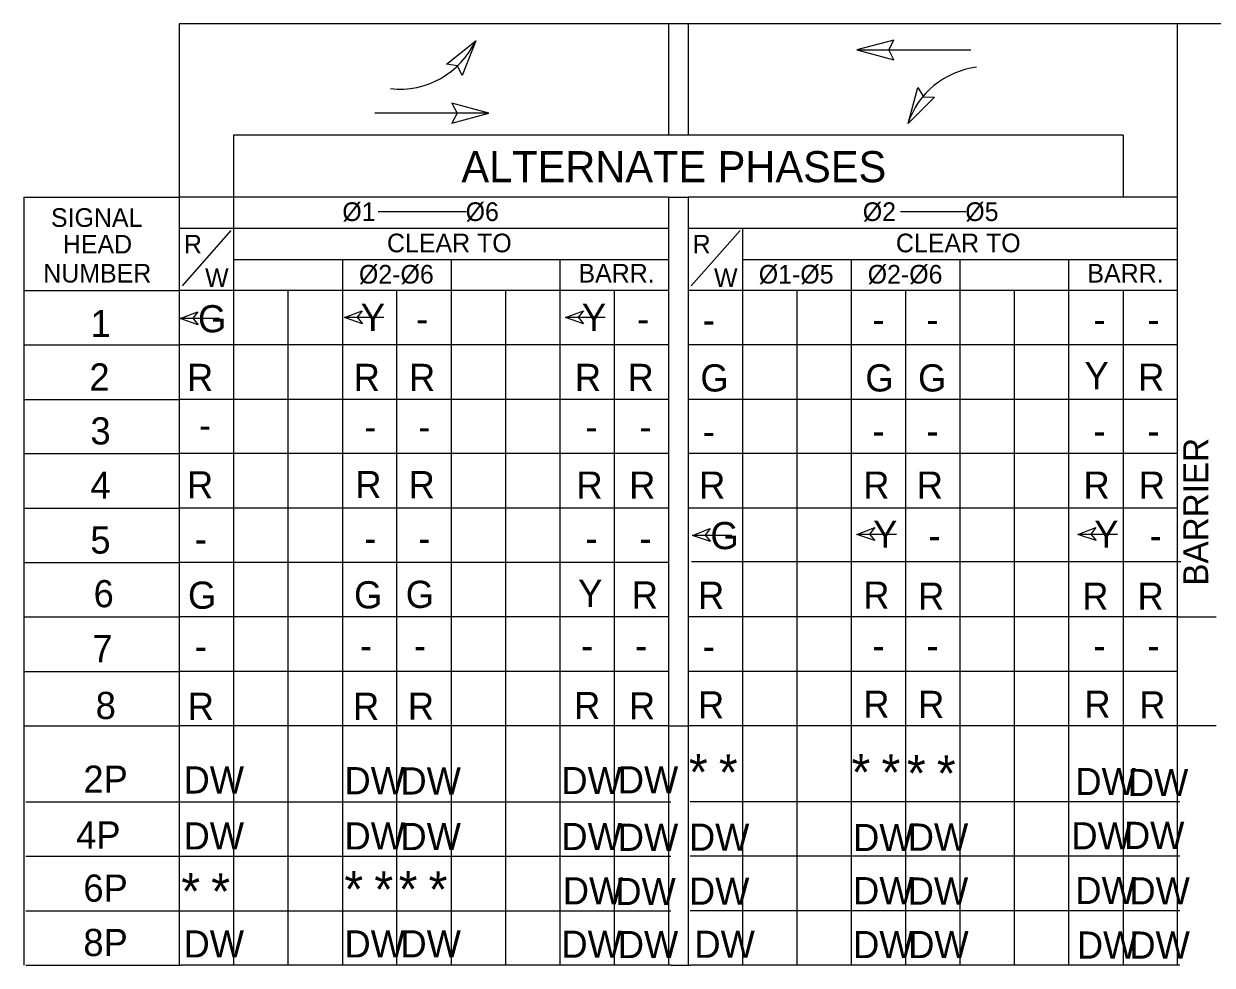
# Model space of a CAD drawing. Extents: x 0 to 3.01, y -0.05 to 1.83.
# Drawn here: x 2.3322 to 2.6407, y 1.0091 to 1.2534 of the extents above; entities that cross this region are included whole.
import ezdxf

# ---------------------------------------------------------------- set-up
doc = ezdxf.new("R2010")
doc.units = 0
for name, color, linetype in [('TR_TS_Border', 7, 'Continuous'), ('TR_TS_Phase1', 7, 'Continuous'), ('TR_TS_Phase2', 7, 'Continuous'), ('TR_TS_Phase3', 7, 'Continuous'), ('TR_TS_Phase4', 7, 'Continuous'), ('TR_TS_Phase5', 7, 'Continuous'), ('TR_TS_Phase6', 7, 'Continuous'), ('TR_TS_Phase7', 7, 'Continuous'), ('TR_TS_Phase8', 7, 'Continuous')]:
    doc.layers.add(name, color=color, linetype=linetype)

msp = doc.modelspace()

# ---------------------------------------------------------------- linework, layer by layer
at = {"layer": 'TR_TS_Border'}
for p, q in [((2.372526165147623, 1.2534462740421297), (2.372526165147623, 1.2084390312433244)), ((2.900956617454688, 1.2534462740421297), (2.372526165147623, 1.2534462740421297)), ((2.4995983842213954, 1.2534461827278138), (2.4995983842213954, 1.2245734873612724)), ((2.504660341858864, 1.2534461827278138), (2.504660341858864, 1.2245734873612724)), ((2.6317323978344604, 1.009138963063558), (2.6317323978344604, 1.2534462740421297)), ((2.6176014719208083, 1.2245736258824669), (2.3866570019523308, 1.2245736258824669)), ((2.3866570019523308, 1.2245736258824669), (2.3866570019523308, 1.2003716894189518)), ((2.6176014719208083, 1.2245736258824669), (2.6176014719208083, 1.2084390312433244)), ((2.332189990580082, 1.2084390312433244), (2.372526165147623, 1.2084390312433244)), ((2.332189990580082, 1.2084390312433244), (2.372526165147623, 1.2084390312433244)), ((2.332189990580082, 1.2084390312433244), (2.332189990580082, 1.009138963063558)), ((2.49959827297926, 1.2084390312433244), (2.372526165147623, 1.2084390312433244)), ((2.372526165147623, 1.2084390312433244), (2.372526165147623, 1.009138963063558)), ((2.49959827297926, 1.2084390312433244), (2.5046602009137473, 1.2084390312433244)), ((2.4995983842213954, 1.2084389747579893), (2.4995983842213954, 1.0091388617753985)), ((2.6317323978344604, 1.2084390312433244), (2.5046602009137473, 1.2084390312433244)), ((2.504660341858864, 1.2084389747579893), (2.504660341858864, 1.0091388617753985)), ((2.424163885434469, 1.2046953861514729), (2.447127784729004, 1.2046953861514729)), ((2.559788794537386, 1.2046953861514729), (2.5768168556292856, 1.2046953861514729)), ((2.372526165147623, 1.2003716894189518), (2.49959827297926, 1.2003716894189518)), ((2.3866570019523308, 1.2003716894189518), (2.3866570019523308, 1.009138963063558)), ((2.5046602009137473, 1.2003716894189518), (2.6317323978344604, 1.2003716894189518)), ((2.5187911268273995, 1.2003716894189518), (2.5187911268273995, 1.009138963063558)), ((2.3733699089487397, 1.185449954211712), (2.3860771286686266, 1.1998447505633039)), ((2.5055037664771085, 1.185449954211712), (2.518158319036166, 1.1998447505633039)), ((2.3866570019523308, 1.192304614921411), (2.49959827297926, 1.192304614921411)), ((2.41491876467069, 1.192304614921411), (2.41491876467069, 1.009138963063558)), ((2.4431276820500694, 1.192304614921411), (2.4431276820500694, 1.009138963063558)), ((2.471389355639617, 1.192304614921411), (2.471389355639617, 1.009138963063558)), ((2.5187911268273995, 1.192304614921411), (2.6317323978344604, 1.192304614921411)), ((2.547000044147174, 1.192304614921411), (2.547000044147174, 1.009138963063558)), ((2.575208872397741, 1.192304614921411), (2.575208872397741, 1.009138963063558)), ((2.6034706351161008, 1.192304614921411), (2.6034706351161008, 1.009138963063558)), ((2.332189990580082, 1.1842374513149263), (2.372526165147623, 1.1842374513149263)), ((2.332189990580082, 1.1842374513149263), (2.372526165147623, 1.1842374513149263)), ((2.49959827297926, 1.1842374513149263), (2.372526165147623, 1.1842374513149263)), ((2.4007879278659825, 1.1842374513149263), (2.4007879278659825, 1.009138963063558)), ((2.4289967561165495, 1.1842374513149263), (2.4289967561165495, 1.009138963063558)), ((2.457258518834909, 1.1842374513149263), (2.457258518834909, 1.009138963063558)), ((2.485467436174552, 1.1842374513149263), (2.485467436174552, 1.009138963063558)), ((2.6317323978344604, 1.1842374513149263), (2.5046602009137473, 1.1842374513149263)), ((2.5328691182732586, 1.1842374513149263), (2.5328691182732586, 1.009138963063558)), ((2.5611308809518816, 1.1842374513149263), (2.5611308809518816, 1.009138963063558)), ((2.589339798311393, 1.1842374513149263), (2.589339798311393, 1.009138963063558)), ((2.6176014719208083, 1.1842374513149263), (2.6176014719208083, 1.009138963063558)), ((2.332189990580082, 1.1701066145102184), (2.372526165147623, 1.1701066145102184)), ((2.49959827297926, 1.1701066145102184), (2.372526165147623, 1.1701066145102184)), ((2.6317323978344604, 1.1701066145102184), (2.5046602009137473, 1.1701066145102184)), ((2.332189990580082, 1.155975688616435), (2.372526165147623, 1.155975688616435)), ((2.49959827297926, 1.155975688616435), (2.372526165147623, 1.155975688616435)), ((2.6317323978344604, 1.155975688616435), (2.5046602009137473, 1.155975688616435)), ((2.332189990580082, 1.1418975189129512), (2.372526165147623, 1.1418975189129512)), ((2.49959827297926, 1.1418975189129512), (2.372526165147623, 1.1418975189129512)), ((2.6317323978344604, 1.1418975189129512), (2.5046602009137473, 1.1418975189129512)), ((2.332189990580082, 1.1277666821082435), (2.372526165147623, 1.1277666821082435)), ((2.49959827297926, 1.1277666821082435), (2.372526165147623, 1.1277666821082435)), ((2.6317323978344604, 1.1277666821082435), (2.5046602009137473, 1.1277666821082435)), ((2.332189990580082, 1.113635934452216), (2.372526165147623, 1.113635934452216)), ((2.49959827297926, 1.113635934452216), (2.372526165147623, 1.113635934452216)), ((2.6326358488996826, 1.1138389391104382), (2.5055637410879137, 1.1138389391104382)), ((2.332189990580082, 1.099505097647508), (2.372526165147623, 1.099505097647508)), ((2.49959827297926, 1.099505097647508), (2.372526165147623, 1.099505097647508)), ((2.6317323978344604, 1.099505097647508), (2.5046602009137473, 1.099505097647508)), ((2.6317323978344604, 1.099505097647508), (2.6418031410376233, 1.099505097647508)), ((2.6317323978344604, 1.0712960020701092), (2.6317323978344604, 1.099505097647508)), ((2.332189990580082, 1.085374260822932), (2.372526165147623, 1.085374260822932)), ((2.49959827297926, 1.085374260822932), (2.372526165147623, 1.085374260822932)), ((2.6317323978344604, 1.085374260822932), (2.5046602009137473, 1.085374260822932)), ((2.332189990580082, 1.0712960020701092), (2.372526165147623, 1.0712960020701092)), ((2.49959827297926, 1.0712960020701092), (2.372526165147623, 1.0712960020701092)), ((2.49959827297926, 1.0712960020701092), (2.5046602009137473, 1.0712960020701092)), ((2.6317323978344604, 1.0712960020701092), (2.5046602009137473, 1.0712960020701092)), ((2.6418031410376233, 1.0712960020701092), (2.6317323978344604, 1.0712960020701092)), ((2.332767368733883, 1.05153174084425), (2.500175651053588, 1.05153174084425)), ((2.6323097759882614, 1.05153174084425), (2.505237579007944, 1.05153174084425)), ((2.332767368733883, 1.037400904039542), (2.500175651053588, 1.037400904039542)), ((2.6323097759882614, 1.037400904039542), (2.505237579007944, 1.037400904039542)), ((2.332767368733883, 1.0232697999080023), (2.500175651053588, 1.0232697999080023)), ((2.6323097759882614, 1.0232697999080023), (2.505237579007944, 1.0232697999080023)), ((2.332767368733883, 1.009138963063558), (2.3731033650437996, 1.009138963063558)), ((2.500175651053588, 1.009138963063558), (2.3731033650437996, 1.009138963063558)), ((2.500175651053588, 1.009138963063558), (2.505237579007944, 1.009138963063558)), ((2.6323097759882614, 1.009138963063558), (2.505237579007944, 1.009138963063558))]:
    msp.add_line(p, q, dxfattribs=at)
at = {"layer": 'TR_TS_Phase1'}
for p, q in [((2.441983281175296, 1.2429842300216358), (2.4495233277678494, 1.249035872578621)), ((2.4495233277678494, 1.249035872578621), (2.446001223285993, 1.2400106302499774)), ((2.4447573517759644, 1.2425358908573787), (2.441983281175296, 1.2429842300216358)), ((2.446001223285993, 1.2400106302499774), (2.4447573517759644, 1.2425358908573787)), ((2.3727537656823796, 1.1769577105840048), (2.3773882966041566, 1.178720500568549)), ((2.3773882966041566, 1.178720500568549), (2.3760588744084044, 1.1770165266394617)), ((2.4154507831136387, 1.1772186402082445), (2.4200853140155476, 1.1789814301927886)), ((2.4200853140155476, 1.1789814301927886), (2.4187558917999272, 1.177277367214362)), ((2.47285886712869, 1.1772186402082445), (2.4774934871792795, 1.1789814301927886)), ((2.4774934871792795, 1.1789814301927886), (2.4761639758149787, 1.177277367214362)), ((2.383015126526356, 1.1769577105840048), (2.3727537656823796, 1.1769577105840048)), ((2.377432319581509, 1.175349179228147), (2.3727537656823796, 1.1769577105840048)), ((2.3760588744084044, 1.1770165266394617), (2.377432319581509, 1.175349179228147)), ((2.4257119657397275, 1.1772186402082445), (2.4154507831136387, 1.1772186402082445)), ((2.420129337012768, 1.1756101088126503), (2.4154507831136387, 1.1772186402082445)), ((2.4187558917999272, 1.177277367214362), (2.420129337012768, 1.1756101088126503)), ((2.4831199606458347, 1.1772186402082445), (2.47285886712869, 1.1772186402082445)), ((2.4775375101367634, 1.1756101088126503), (2.47285886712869, 1.1772186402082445)), ((2.4761639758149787, 1.177277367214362), (2.4775375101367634, 1.1756101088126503))]:
    msp.add_line(p, q, dxfattribs=at)
msp.add_arc((2.4298384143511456, 1.2581039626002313), 0.02161745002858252, 263.56145, 335.3874333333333, dxfattribs=at)
at = {"layer": 'TR_TS_Phase2'}
for p, q in [((2.5580969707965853, 1.2492355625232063), (2.5484725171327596, 1.246644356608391)), ((2.5484725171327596, 1.246644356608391), (2.5580969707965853, 1.2440530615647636)), ((2.5484725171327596, 1.246644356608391), (2.578092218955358, 1.246644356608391)), ((2.556764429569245, 1.246644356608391), (2.5580969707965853, 1.2492355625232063)), ((2.5580969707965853, 1.2440530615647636), (2.556764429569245, 1.246644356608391))]:
    msp.add_line(p, q, dxfattribs=at)
at = {"layer": 'TR_TS_Phase5'}
for p, q in [((2.5617785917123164, 1.2275463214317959), (2.5642972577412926, 1.2369013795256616)), ((2.5686148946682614, 1.234382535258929), (2.5617785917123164, 1.2275463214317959)), ((2.5642972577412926, 1.2369013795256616), (2.565808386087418, 1.234526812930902)), ((2.565808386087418, 1.234526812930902), (2.5686148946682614, 1.234382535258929)), ((2.5057912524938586, 1.120690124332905), (2.5104258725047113, 1.122452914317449)), ((2.5160527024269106, 1.120690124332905), (2.5057912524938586, 1.120690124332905)), ((2.510469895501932, 1.119081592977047), (2.5057912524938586, 1.120690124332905)), ((2.5104258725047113, 1.122452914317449), (2.5090963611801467, 1.1207488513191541)), ((2.5090963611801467, 1.1207488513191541), (2.510469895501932, 1.119081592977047)), ((2.5484883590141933, 1.1209510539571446), (2.553122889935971, 1.1227136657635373)), ((2.558749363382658, 1.1209510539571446), (2.5484883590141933, 1.1209510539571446)), ((2.5531669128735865, 1.119342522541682), (2.5484883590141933, 1.1209510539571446)), ((2.553122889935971, 1.1227136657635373), (2.5517934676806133, 1.1210097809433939)), ((2.5517934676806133, 1.1210097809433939), (2.5531669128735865, 1.119342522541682)), ((2.6058964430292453, 1.1209510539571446), (2.610530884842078, 1.1227136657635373)), ((2.616157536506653, 1.1209510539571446), (2.6058964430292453, 1.1209510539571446)), ((2.6105750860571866, 1.119342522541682), (2.6058964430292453, 1.1209510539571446)), ((2.610530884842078, 1.1227136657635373), (2.6092015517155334, 1.1210097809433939)), ((2.6092015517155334, 1.1210097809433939), (2.6105750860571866, 1.119342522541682))]:
    msp.add_line(p, q, dxfattribs=at)
msp.add_arc((2.5822266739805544, 1.2207117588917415), 0.021617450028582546, 97.19140000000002, 161.63656666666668, dxfattribs=at)
at = {"layer": 'TR_TS_Phase6'}
for p, q in [((2.44334487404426, 1.2328371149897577), (2.4446775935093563, 1.230245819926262)), ((2.4529695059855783, 1.230245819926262), (2.44334487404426, 1.2328371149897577)), ((2.4529695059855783, 1.230245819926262), (2.423349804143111, 1.230245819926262)), ((2.4446775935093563, 1.230245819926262), (2.44334487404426, 1.2276545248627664)), ((2.44334487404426, 1.2276545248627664), (2.4529695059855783, 1.230245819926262))]:
    msp.add_line(p, q, dxfattribs=at)

# ---------------------------------------------------------------- texts
at = {"layer": 'TR_TS_Border'}
for s, height, rotation, p in [('ALTERNATE PHASES', 0.00806692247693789, 360, (2.4458144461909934, 1.2123248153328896)), ('Ø1             Ø6', 0.004840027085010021, 360, (2.4149008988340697, 1.202269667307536)), ('Ø2          Ø5', 0.004840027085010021, 360, (2.5500193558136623, 1.202269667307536)), ('SIGNAL', 0.004840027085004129, 360, (2.339254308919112, 1.2007408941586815)), ('HEAD', 0.004840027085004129, 360, (2.3423287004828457, 1.1938336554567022)), ('R', 0.004840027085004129, 360, (2.3737769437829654, 1.1938336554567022)), ('CLEAR TO', 0.004840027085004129, 360, (2.426494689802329, 1.1941499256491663)), ('R', 0.004840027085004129, 360, (2.5058581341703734, 1.1938336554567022)), ('CLEAR TO', 0.004840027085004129, 360, (2.5586285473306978, 1.1941499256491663)), ('NUMBER', 0.004840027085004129, 360, (2.3372516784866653, 1.186293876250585)), ('Ø2-Ø6', 0.004840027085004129, 360, (2.41921221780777, 1.186030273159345)), ('BARR.', 0.004840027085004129, 360, (2.476212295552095, 1.186293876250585)), ('Ø1-Ø5', 0.004840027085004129, 360, (2.523020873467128, 1.186030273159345)), ('Ø2-Ø6', 0.004840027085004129, 360, (2.551293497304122, 1.186030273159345)), ('BARR.', 0.004840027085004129, 360, (2.6083460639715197, 1.186293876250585)), ('W', 0.004840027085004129, 360, (2.379270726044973, 1.1851340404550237)), ('W', 0.004840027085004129, 360, (2.511405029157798, 1.1851340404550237)), ('BARRIER', 0.006449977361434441, 89.99999722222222, (2.639694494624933, 1.1076385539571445))]:
    msp.add_text(s, height=height, rotation=rotation, dxfattribs=at).set_placement(p)
msp.add_text('*', height=0.009384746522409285, dxfattribs=at).set_placement((2.3808576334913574, 1.0235915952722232))
at = {"layer": 'TR_TS_Phase1'}
for s, p in [('1', (2.349557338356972, 1.1721542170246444)), ('G', (2.3774308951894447, 1.1733768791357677)), ('Y', (2.4196802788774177, 1.1737305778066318)), ('Y', (2.477088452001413, 1.1737305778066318)), ('-', (2.4340505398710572, 1.1733768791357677)), ('-', (2.4914587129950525, 1.1733768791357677)), ('-', (2.5084937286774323, 1.1730792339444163)), ('-', (2.552511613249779, 1.1732352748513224)), ('-', (2.5665458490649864, 1.1732352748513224)), ('-', (2.609919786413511, 1.1732352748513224)), ('-', (2.623953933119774, 1.1732352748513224))]:
    msp.add_text(s, height=0.007050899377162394, dxfattribs=at).set_placement(p)
at = {"layer": 'TR_TS_Phase2'}
for s, height, p in [('2', 0.007050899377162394, (2.349230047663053, 1.1582786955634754)), ('R', 0.007050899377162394, (2.3745667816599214, 1.158150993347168)), ('R', 0.007050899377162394, (2.417850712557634, 1.158150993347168)), ('R', 0.007050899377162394, (2.43220407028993, 1.158150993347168)), ('R', 0.007050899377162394, (2.47526396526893, 1.158150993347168)), ('R', 0.007050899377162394, (2.488944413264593, 1.158150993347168)), ('G', 0.007050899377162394, (2.507862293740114, 1.1580243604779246)), ('G', 0.007050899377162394, (2.55069779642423, 1.1580243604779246)), ('G', 0.007050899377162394, (2.564378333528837, 1.1580243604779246)), ('*', 0.009384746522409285, (2.504883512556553, 1.0545504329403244)), ('*', 0.009384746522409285, (2.512653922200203, 1.0544942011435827)), ('*', 0.009384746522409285, (2.547109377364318, 1.0545466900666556)), ('*', 0.009384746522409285, (2.554879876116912, 1.0544904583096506)), ('*', 0.009384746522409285, (2.561487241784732, 1.0542803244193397)), ('*', 0.009384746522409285, (2.5692576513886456, 1.0542240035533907)), ('2P', 0.007050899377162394, (2.34766512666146, 1.0538891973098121)), ('DW', 0.007050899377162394, (2.373667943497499, 1.0537004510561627)), ('DW', 0.007050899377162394, (2.4154547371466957, 1.0535079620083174)), ('DW', 0.007050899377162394, (2.4299828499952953, 1.053439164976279)), ('DW', 0.007050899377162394, (2.4717697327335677, 1.0535353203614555)), ('DW', 0.007050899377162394, (2.4864118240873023, 1.053727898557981)), ('DW', 0.007050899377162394, (2.605211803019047, 1.0532811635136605)), ('DW', 0.007050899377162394, (2.6188415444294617, 1.053044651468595))]:
    msp.add_text(s, height=height, dxfattribs=at).set_placement(p)
for s, p in [('Y', (2.607588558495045, 1.1586102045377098)), ('R', (2.62150771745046, 1.1582365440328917))]:
    msp.add_text(s, height=0.007050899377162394, rotation=360, dxfattribs=at).set_placement(p)
at = {"layer": 'TR_TS_Phase3'}
for s, p in [('3', (2.349501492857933, 1.1442760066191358)), ('-', (2.3776828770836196, 1.1457810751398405)), ('-', (2.4205875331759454, 1.1453801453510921)), ('-', (2.4346216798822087, 1.1453801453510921)), ('-', (2.4779956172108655, 1.1453801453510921)), ('-', (2.4920298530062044, 1.1453801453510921)), ('-', (2.5084937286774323, 1.1441097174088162)), ('-', (2.552511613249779, 1.1442658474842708)), ('-', (2.5665458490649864, 1.1442658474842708)), ('-', (2.609919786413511, 1.1442658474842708)), ('-', (2.623953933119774, 1.1442658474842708))]:
    msp.add_text(s, height=0.007050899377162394, dxfattribs=at).set_placement(p)
at = {"layer": 'TR_TS_Phase4'}
for s, p in [('4', (2.3495017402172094, 1.130190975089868)), ('R', (2.3745667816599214, 1.1302819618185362)), ('R', (2.418273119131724, 1.130346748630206)), ('R', (2.4321070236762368, 1.1303229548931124)), ('R', (2.47568129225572, 1.1302016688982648)), ('R', (2.4893617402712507, 1.1302016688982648)), ('R', (2.507527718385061, 1.1302016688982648)), ('R', (2.5501390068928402, 1.1302016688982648)), ('R', (2.5640436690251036, 1.1302016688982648)), ('R', (2.6073275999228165, 1.1302016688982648)), ('R', (2.621680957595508, 1.1302016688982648)), ('4P', (2.3457801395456, 1.0394158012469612)), ('DW', (2.373667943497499, 1.0391704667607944)), ('DW', (2.4154547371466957, 1.0391704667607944)), ('DW', (2.4299828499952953, 1.0390056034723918)), ('DW', (2.4717697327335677, 1.0390056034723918)), ('DW', (2.6041835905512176, 1.0392038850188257)), ('DW', (2.617812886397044, 1.039316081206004)), ('DW', (2.4864118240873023, 1.0388130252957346)), ('DW', (2.504882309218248, 1.0388506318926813)), ('DW', (2.5475048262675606, 1.038755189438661)), ('DW', (2.56169474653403, 1.0388673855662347))]:
    msp.add_text(s, height=0.007050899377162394, dxfattribs=at).set_placement(p)
at = {"layer": 'TR_TS_Phase5'}
for s, p in [('G', (2.5104684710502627, 1.1171092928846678)), ('Y', (2.552717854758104, 1.1174629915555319)), ('Y', (2.610126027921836, 1.1174629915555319)), ('5', (2.3494735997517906, 1.1159558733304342)), ('-', (2.567088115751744, 1.1171092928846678)), ('-', (2.6244962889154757, 1.1171092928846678)), ('-', (2.3765696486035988, 1.11625467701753)), ('-', (2.4205875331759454, 1.116410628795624)), ('-', (2.4346216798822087, 1.116410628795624)), ('-', (2.4779956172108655, 1.116410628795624)), ('-', (2.4920298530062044, 1.116410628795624))]:
    msp.add_text(s, height=0.007050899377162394, dxfattribs=at).set_placement(p)
at = {"layer": 'TR_TS_Phase6'}
for s, height, p in [('6', 0.007050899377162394, (2.3503164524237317, 1.1020384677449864)), ('G', 0.007050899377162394, (2.374824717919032, 1.1016403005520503)), ('G', 0.007050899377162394, (2.4179297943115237, 1.1017366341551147)), ('G', 0.007050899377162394, (2.4313625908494, 1.1018572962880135)), ('R', 0.007050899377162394, (2.507247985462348, 1.1016211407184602)), ('R', 0.007050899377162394, (2.5501525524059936, 1.1016536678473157)), ('R', 0.007050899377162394, (2.5643875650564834, 1.1013816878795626)), ('R', 0.007050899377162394, (2.606998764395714, 1.1013816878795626)), ('R', 0.007050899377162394, (2.6213519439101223, 1.1013816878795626)), ('6P', 0.007050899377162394, (2.34766512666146, 1.0256295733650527)), ('*', 0.009384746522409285, (2.373087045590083, 1.0236478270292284)), ('*', 0.009384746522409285, (2.415421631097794, 1.0241806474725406)), ('*', 0.009384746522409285, (2.423192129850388, 1.0241243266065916)), ('*', 0.009384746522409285, (2.429533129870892, 1.0241806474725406)), ('*', 0.009384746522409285, (2.43730371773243, 1.0241243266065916)), ('DW', 0.007050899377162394, (2.4721401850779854, 1.0249207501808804)), ('DW', 0.007050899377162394, (2.4857699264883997, 1.0247475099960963)), ('DW', 0.007050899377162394, (2.504882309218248, 1.0248230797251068)), ('DW', 0.007050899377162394, (2.5475048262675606, 1.0249676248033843)), ('DW', 0.007050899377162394, (2.56169474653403, 1.024855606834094)), ('DW', 0.007050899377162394, (2.605211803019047, 1.0250215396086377)), ('DW', 0.007050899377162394, (2.6192310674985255, 1.024909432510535))]:
    msp.add_text(s, height=height, dxfattribs=at).set_placement(p)
for s, p in [('Y', (2.476121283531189, 1.102105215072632)), ('R', (2.4900404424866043, 1.1016992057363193))]:
    msp.add_text(s, height=0.007050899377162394, rotation=360, dxfattribs=at).set_placement(p)
at = {"layer": 'TR_TS_Phase7'}
for s, p in [('7', (2.349997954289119, 1.087772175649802)), ('-', (2.3765696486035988, 1.0883991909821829)), ('-', (2.4194743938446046, 1.0885554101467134)), ('-', (2.4335086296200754, 1.0885554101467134)), ('-', (2.4768825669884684, 1.0885554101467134)), ('-', (2.4909167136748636, 1.0885554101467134)), ('-', (2.5084937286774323, 1.0883991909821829)), ('-', (2.552511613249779, 1.0885554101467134)), ('-', (2.5665458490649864, 1.0885554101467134)), ('-', (2.609919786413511, 1.0885554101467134)), ('-', (2.623953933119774, 1.0885554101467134))]:
    msp.add_text(s, height=0.007050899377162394, dxfattribs=at).set_placement(p)
at = {"layer": 'TR_TS_Phase8'}
for s, p in [('8', (2.350859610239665, 1.073023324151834)), ('R', (2.475079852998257, 1.0729960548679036)), ('R', (2.489314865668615, 1.0729164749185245)), ('R', (2.507247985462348, 1.073188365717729)), ('R', (2.5501525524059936, 1.0733492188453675)), ('R', (2.5643875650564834, 1.0733018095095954)), ('R', (2.607560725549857, 1.0733492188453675)), ('R', (2.6217955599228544, 1.073189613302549)), ('R', (2.3747671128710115, 1.0728035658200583)), ('R', (2.417671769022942, 1.0728035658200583)), ('R', (2.4319066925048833, 1.072820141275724)), ('8P', (2.34766512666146, 1.0115142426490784)), ('DW', (2.373667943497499, 1.0111424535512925)), ('DW', (2.4154547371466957, 1.0111424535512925)), ('DW', (2.4299828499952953, 1.0111698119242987)), ('DW', (2.4717697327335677, 1.0110736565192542)), ('DW', (2.4864118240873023, 1.010977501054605)), ('DW', (2.5063000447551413, 1.0110650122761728)), ('DW', (2.5475048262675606, 1.0109769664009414)), ('DW', (2.561807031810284, 1.0109769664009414)), ('DW', (2.605601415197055, 1.0108410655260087)), ('DW', (2.619230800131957, 1.0108410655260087))]:
    msp.add_text(s, height=0.007050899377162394, dxfattribs=at).set_placement(p)

doc.saveas('drawing.dxf')
